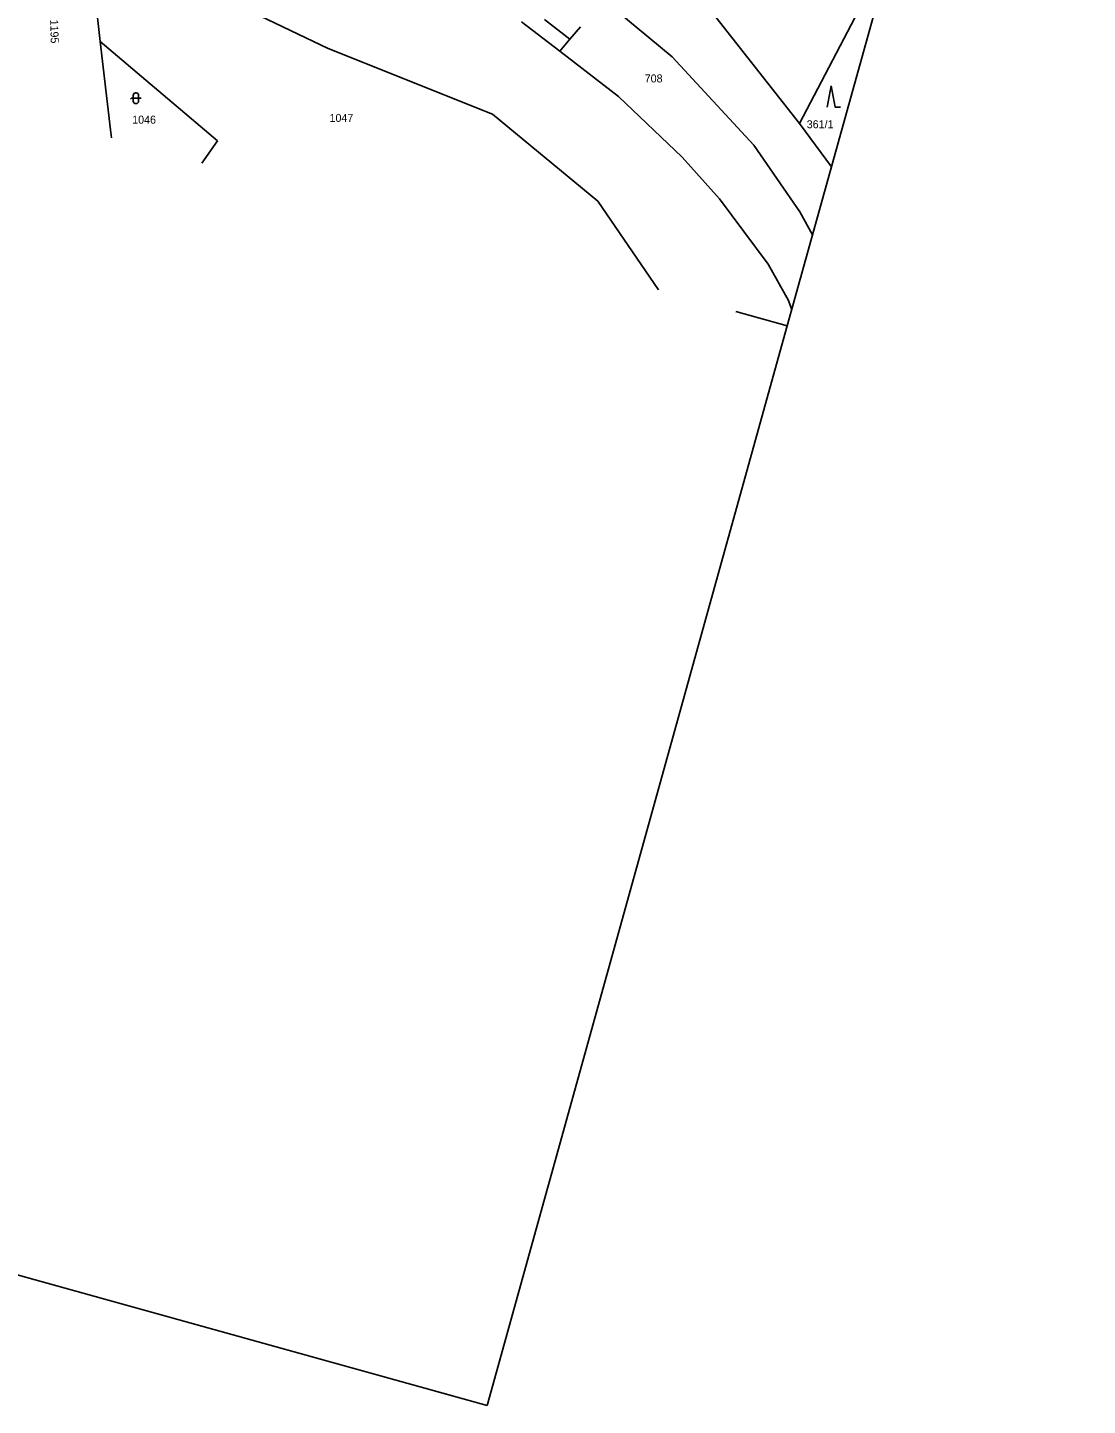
# Model space of a CAD drawing. Extents: x -795046 to -794647, y -1136002 to -1135518.
# Drawn here: x -794845.7 to -794647.1, y -1136002.2 to -1135744 of the extents above; entities that cross this region are included whole.
import ezdxf

# ---------------------------------------------------------------- set-up
doc = ezdxf.new("R2010")
doc.units = 0
for name, color, linetype in [('Default', 7, 'Continuous'), ('formát', 7, 'Continuous'), ('kn_celek - Cisla pozemkovych parcel', 7, 'Continuous'), ('kn_celek - Hranice parcel', 7, 'Continuous'), ('kn_celek - Vnitrni kresby', 7, 'Continuous'), ('kn_celek - Znacky kultur', 7, 'Continuous')]:
    doc.layers.add(name, color=color, linetype=linetype)

# ---------------------------------------------------------------- blocks, each defined once
blk = doc.blocks.new('308')
at = {"layer": 'Default'}
for p, q in [((-7.5, 0.2), (0, 40.2)), ((0, 40.2), (7.5, 0.2)), ((7.5, 0.2), (17.5, 0.2))]:
    blk.add_line(p, q, dxfattribs=at)
blk = doc.blocks.new('316')
at = {"layer": 'Default'}
for p, q in [((-8.3, 10), (-10, 8.1)), ((-5, 10), (-8.3, 10)), ((-5, 15.5), (-5, 4.5)), ((-5, 10), (5, 10)), ((0.5, 20), (-0.5, 20)), ((-0.5, 0), (0.5, 0)), ((5, 4.5), (5, 15.5)), ((10, 10), (5, 10))]:
    blk.add_line(p, q, dxfattribs=at)
for centre, start, end in [((-0.5, 15.5), 90, 180), ((-0.5, 4.5), 180, 270), ((0.5, 15.5), 0, 90), ((0.5, 4.5), 270, 0)]:
    blk.add_arc(centre, 4.5, start, end, dxfattribs=at)

msp = doc.modelspace()

# ---------------------------------------------------------------- linework, layer by layer
at = {"layer": 'formát'}
for p, q in [((-794647.13, -1135597.56), (-794703.39, -1135799.88)), ((-794713.02, -1135797.2), (-794703.39, -1135799.88)), ((-794713.02, -1135797.2), (-794703.39, -1135799.88)), ((-794703.39, -1135799.88), (-794759.64, -1136002.21)), ((-795045.79, -1135922.65), (-794759.64, -1136002.21)), ((-794769.27, -1135999.53), (-794759.64, -1136002.21))]:
    msp.add_line(p, q, dxfattribs=at)
at = {"layer": 'kn_celek - Hranice parcel'}
for p, q in [((-794834.7, -1135724.35), (-794832.11, -1135746.62)), ((-794727.83, -1135728.01), (-794701.06, -1135761.99)), ((-794683.52, -1135728.41), (-794701.06, -1135761.99)), ((-794724.97, -1135749.47), (-794737.72, -1135738.96)), ((-794803.54, -1135741.17), (-794789.42, -1135747.91)), ((-794753.16, -1135742.91), (-794746.01, -1135748.41)), ((-794744.13, -1135746.19), (-794742.14, -1135743.85)), ((-794832.11, -1135746.62), (-794830.18, -1135763.2)), ((-794832.11, -1135746.62), (-794810.12, -1135765.23)), ((-794789.42, -1135747.91), (-794758.65, -1135760.23)), ((-794746.01, -1135748.41), (-794744.13, -1135746.19)), ((-794735.01, -1135756.9), (-794746.01, -1135748.41)), ((-794709.64, -1135766.06), (-794724.97, -1135749.47)), ((-794723.06, -1135768.28), (-794735.01, -1135756.9)), ((-794758.65, -1135760.23), (-794738.86, -1135776.53)), ((-794830.18, -1135763.2), (-794830.01, -1135764.68)), ((-794701.06, -1135761.99), (-794695.11, -1135770.12)), ((-794810.12, -1135765.23), (-794813.08, -1135769.39)), ((-794701.05, -1135778.57), (-794709.64, -1135766.06)), ((-794716.06, -1135776.1), (-794723.06, -1135768.28)), ((-794738.86, -1135776.53), (-794727.52, -1135793.17)), ((-794706.99, -1135788.32), (-794716.06, -1135776.1)), ((-794698.65, -1135782.83), (-794701.05, -1135778.57)), ((-794703.13, -1135795.18), (-794706.99, -1135788.32)), ((-794702.55, -1135796.88), (-794703.13, -1135795.18))]:
    msp.add_line(p, q, dxfattribs=at)
at = {"layer": 'kn_celek - Vnitrni kresby'}
msp.add_line((-794748.9, -1135742.47), (-794744.13, -1135746.19), dxfattribs=at)

# ---------------------------------------------------------------- block references
at = {"layer": 'kn_celek - Znacky kultur', "xscale": 0.1, "yscale": 0.10000000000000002}
for name, p in [('308', (-794695.16, -1135758.97)), ('316', (-794825.44, -1135758.26))]:
    msp.add_blockref(name, p, dxfattribs=at)

# ---------------------------------------------------------------- texts
at = {"layer": 'kn_celek - Cisla pozemkovych parcel'}
msp.add_text('1195', height=1.5, rotation=271.756, dxfattribs=at).set_placement((-794841.52, -1135742.54))
for s, p in [('708', (-794730.1, -1135754.29)), ('1046', (-794826.14, -1135762.02)), ('1047', (-794789.16, -1135761.69)), ('361/1', (-794699.74, -1135762.88))]:
    msp.add_text(s, height=1.5, dxfattribs=at).set_placement(p)

doc.saveas('drawing.dxf')
